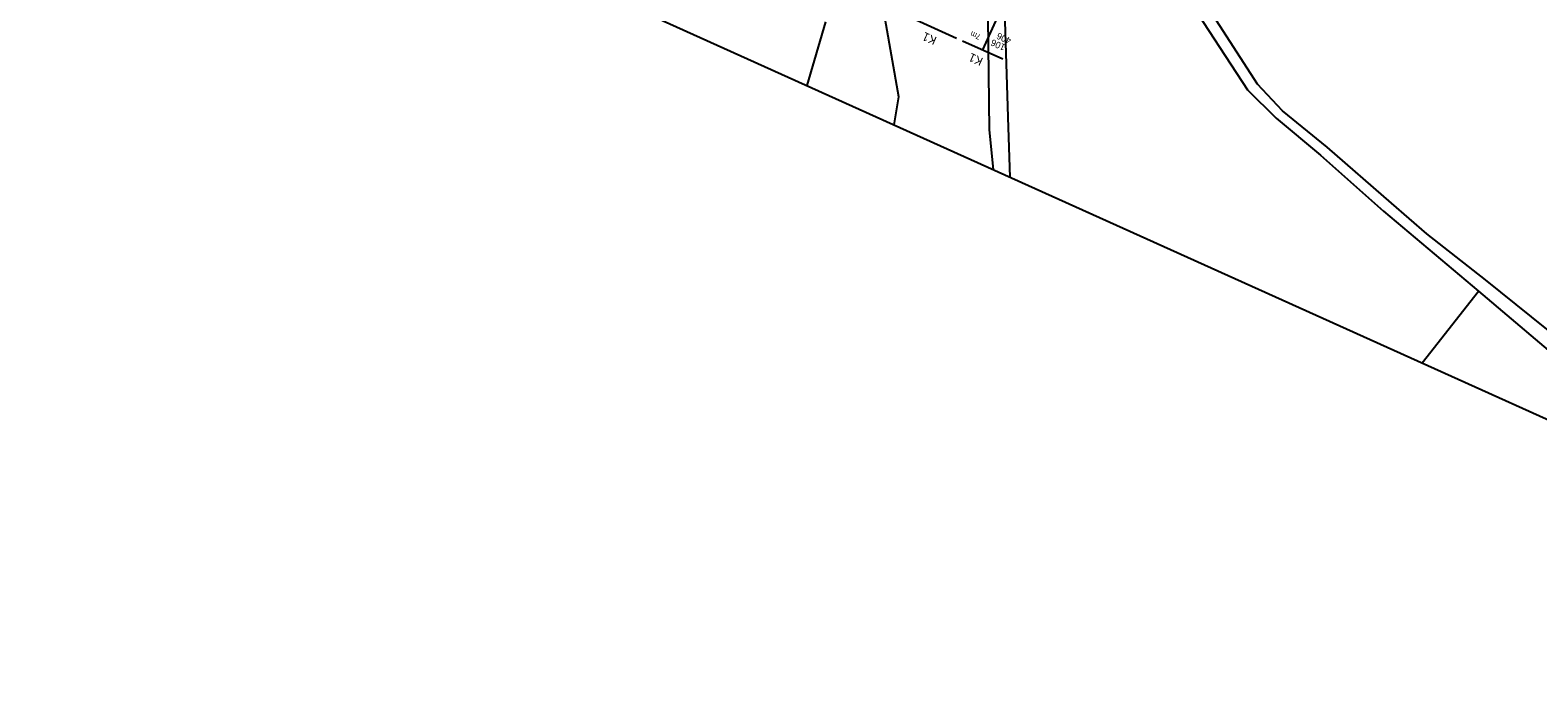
# Model space of a CAD drawing. Extents: x -621716 to -621020, y -1122350 to -1121821.
# Drawn here: x -621716.4 to -621307, y -1122350.4 to -1122171.6 of the extents above; entities that cross this region are included whole.
import ezdxf

# ---------------------------------------------------------------- set-up
doc = ezdxf.new("R2010")
doc.units = 0
for name, color, linetype in [('Hranice parcel', 7, 'Continuous'), ('Rámečky-tisk', 7, 'Continuous'), ('Vrstva 33', 7, 'Continuous')]:
    doc.layers.add(name, color=color, linetype=linetype)

msp = doc.modelspace()

# ---------------------------------------------------------------- linework, layer by layer
at = {"layer": 'Hranice parcel'}
for p, q in [((-621407.95, -1122153.65), (-621385.83, -1122187.85)), ((-621407.95, -1122153.65), (-621385.83, -1122187.85)), ((-621500.39, -1122169.33), (-621505.47, -1122186.6)), ((-621500.39, -1122169.33), (-621505.47, -1122186.6)), ((-621348.86, -1122220.77), (-621323.04, -1122242.46)), ((-621348.86, -1122220.77), (-621323.04, -1122242.46)), ((-621323.04, -1122242.46), (-621290.49, -1122270.16)), ((-621323.04, -1122242.46), (-621290.49, -1122270.16))]:
    msp.add_line(p, q, dxfattribs=at)
for points in [[(-621236.42, -1122307.9), (-621250, -1122296.86), (-621287.36, -1122266.52), (-621321.13, -1122239.4), (-621337.07, -1122226.87), (-621346.7, -1122218.55), (-621364.2, -1122203.4), (-621376.27, -1122193.53), (-621383.11, -1122186.25), (-621403.55, -1122154.5), (-621447.98, -1122102.71)], [(-621450.22, -1122211.51), (-621450.7, -1122198.05), (-621453.42, -1122111.52)], [(-621454.75, -1122209.47), (-621455.81, -1122198.63), (-621456.82, -1122115.07)], [(-621481.7, -1122197.32), (-621480.51, -1122189.68), (-621487.9, -1122147.44)], [(-621385.83, -1122187.85), (-621378.02, -1122195.51), (-621365.96, -1122205.51), (-621348.86, -1122220.77)], [(-621385.83, -1122187.85), (-621378.02, -1122195.51), (-621365.96, -1122205.51), (-621348.86, -1122220.77)], [(-621338.34, -1122261.95), (-621323.04, -1122242.46)]]:
    msp.add_lwpolyline(points, dxfattribs=at)
at = {"layer": 'Rámečky-tisk'}
msp.add_lwpolyline([(-621594.3, -1121820.78), (-621716.36, -1122091.54), (-621142.02, -1122350.45)], dxfattribs=at)
at = {"layer": 'Vrstva 33'}
for p, q in [((-621408.47, -1122067.72), (-621457.71, -1122176.95)), ((-621475.76, -1122168.81), (-621464.82, -1122173.74)), ((-621463.18, -1122174.48), (-621452.24, -1122179.42))]:
    msp.add_line(p, q, dxfattribs=at)

# ---------------------------------------------------------------- texts
for s, height, p in [('K1', 2.3, (-621469.99, -1122173.61)), ('7m', 1.5, (-621458.1, -1122172.94)), ('406', 1.8, (-621449.74, -1122173.85)), ('106', 1.8, (-621451.34, -1122175.65)), ('K1', 2.3, (-621457.41, -1122179.28))]:
    msp.add_text(s, height=height, rotation=155.7341, dxfattribs=at).set_placement(p)

doc.saveas('drawing.dxf')
